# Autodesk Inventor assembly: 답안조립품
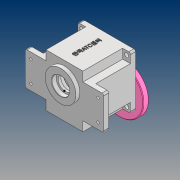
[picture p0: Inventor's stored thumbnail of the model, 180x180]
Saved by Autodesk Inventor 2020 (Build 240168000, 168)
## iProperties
Created: 2020-07
Part Number: 답안조립품
Document SubType Name: Weldment
Designer: PC312-
Weld Material: Welded Aluminum-6061
Author: PC312-
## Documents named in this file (3)
- C:\Users\PC312-\Desktop\700718V1015\답안조립품.iam
- C:\Users\PC312-\Desktop\700718V1015\본체.ipt
- C:\Users\PC312-\Desktop\700718V1015\커버.ipt
